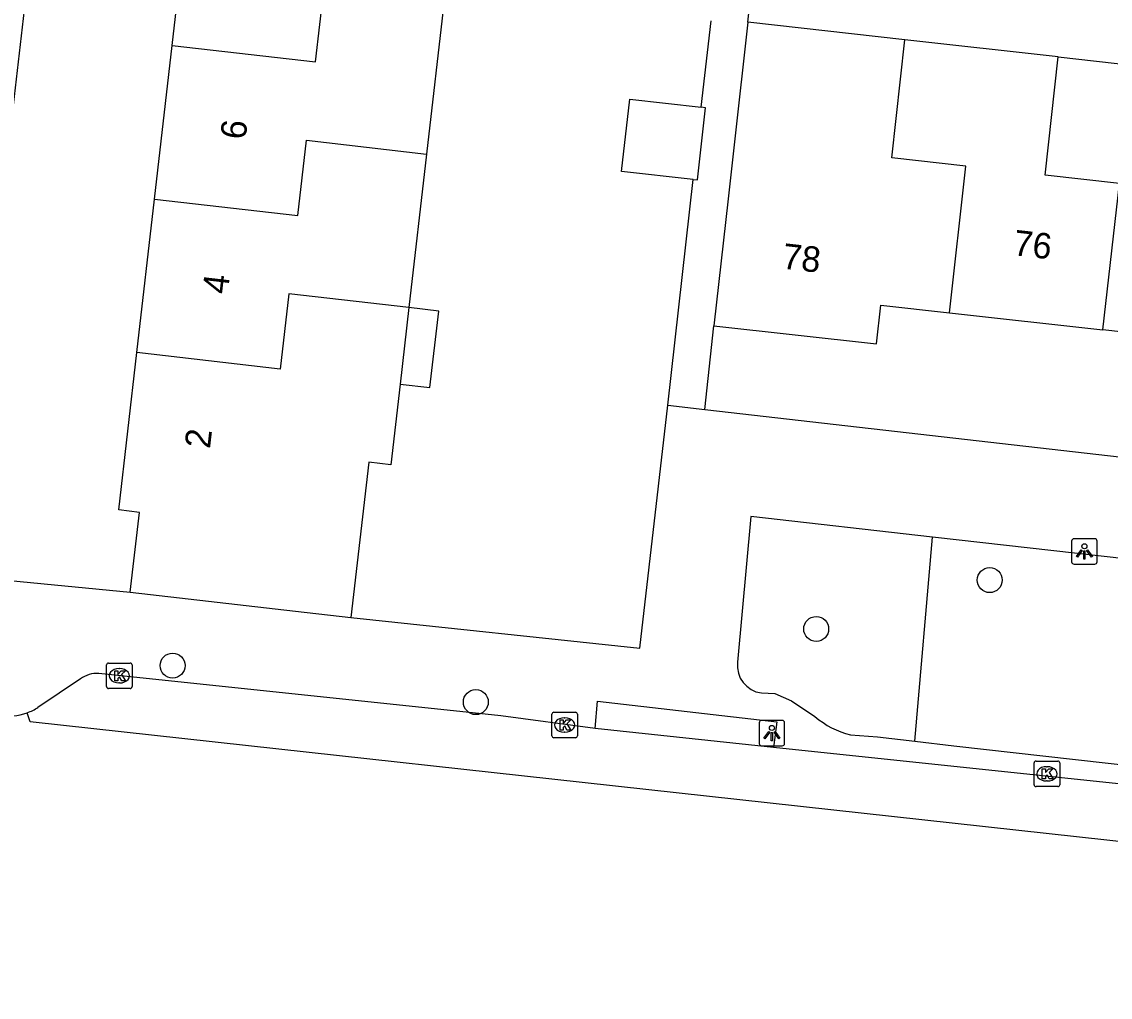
# Model space of a CAD drawing. Extents: x 162082 to 163393, y 388091 to 388632.
# Drawn here: x 162657.96 to 162700.61, y 388094.28 to 388132.52 of the extents above; entities that cross this region are included whole.
import ezdxf

# ---------------------------------------------------------------- set-up
doc = ezdxf.new("R2010")
doc.units = 0
for name, color, linetype in [('IMGEO_Boom', 7, 'Continuous'), ('IMGEO_Groenvoorziening', 7, 'Continuous'), ('IMGEO_Kolk', 7, 'Continuous'), ('IMGEO_Lichtpunt', 7, 'Continuous'), ('IMGEO_Pand', 7, 'Continuous'), ('IMGEO_Pand_nummerreeks', 7, 'Continuous'), ('IMGEO_Pand_overbouw', 7, 'Continuous'), ('IMGEO_Rijbaan_lokaal_gesloten', 7, 'Continuous'), ('IMGEO_Voetpad_open', 7, 'Continuous')]:
    doc.layers.add(name, color=color, linetype=linetype)

msp = doc.modelspace()

# ---------------------------------------------------------------- linework, layer by layer
at = {"layer": 'IMGEO_Boom'}
for centre in [(162695.889, 388110.633), (162689.089, 388108.721), (162663.87, 388107.283), (162675.753, 388105.851)]:
    msp.add_circle(centre, 0.489, dxfattribs=at)
at = {"layer": 'IMGEO_Groenvoorziening'}
msp.add_lwpolyline([(162692.953, 388104.317), (162693.647, 388112.321)], dxfattribs=at)
at = {"layer": 'IMGEO_Kolk'}
for p, q in [((162661.283, 388106.457), (162661.283, 388107.309)), ((162661.358, 388107.383), (162662.21, 388107.383)), ((162661.771, 388107.163), (162661.796, 388107.163)), ((162662.284, 388107.309), (162662.284, 388106.457)), ((162662.21, 388106.383), (162661.358, 388106.383)), ((162661.794, 388106.603), (162661.769, 388106.603)), ((162678.806, 388105.454), (162679.658, 388105.454)), ((162678.731, 388104.528), (162678.731, 388105.38)), ((162679.219, 388105.234), (162679.244, 388105.234)), ((162679.732, 388105.38), (162679.732, 388104.528)), ((162679.242, 388104.674), (162679.217, 388104.674)), ((162679.658, 388104.454), (162678.806, 388104.454)), ((162697.629, 388102.614), (162697.629, 388103.466)), ((162697.704, 388103.54), (162698.556, 388103.54)), ((162698.117, 388103.32), (162698.142, 388103.32)), ((162698.63, 388103.466), (162698.63, 388102.614)), ((162698.556, 388102.54), (162697.704, 388102.54)), ((162698.14, 388102.76), (162698.115, 388102.76))]:
    msp.add_line(p, q, dxfattribs=at)
for points in [[(162661.283, 388106.457), (162661.283, 388107.309)], [(162661.358, 388107.383), (162662.21, 388107.383)], [(162662.284, 388107.309), (162662.284, 388106.457)], [(162661.604, 388107.083), (162661.727, 388107.083), (162661.727, 388106.932), (162661.857, 388107.083), (162662.021, 388107.083), (162661.875, 388106.932), (162662.028, 388106.683), (162661.876, 388106.683), (162661.791, 388106.847), (162661.727, 388106.78), (162661.727, 388106.683), (162661.604, 388106.683), (162661.604, 388107.083)], [(162662.21, 388106.383), (162661.358, 388106.383)], [(162678.806, 388105.454), (162679.658, 388105.454)], [(162678.731, 388104.528), (162678.731, 388105.38)], [(162679.052, 388105.154), (162679.175, 388105.154), (162679.175, 388105.003), (162679.305, 388105.154), (162679.469, 388105.154), (162679.323, 388105.003), (162679.476, 388104.754), (162679.324, 388104.754), (162679.239, 388104.918), (162679.175, 388104.851), (162679.175, 388104.754), (162679.052, 388104.754), (162679.052, 388105.154)], [(162679.732, 388105.38), (162679.732, 388104.528)], [(162679.658, 388104.454), (162678.806, 388104.454)], [(162697.629, 388102.614), (162697.629, 388103.466)], [(162697.704, 388103.54), (162698.556, 388103.54)], [(162698.63, 388103.466), (162698.63, 388102.614)], [(162697.95, 388103.24), (162698.073, 388103.24), (162698.073, 388103.089), (162698.203, 388103.24), (162698.367, 388103.24), (162698.221, 388103.089), (162698.374, 388102.84), (162698.222, 388102.84), (162698.137, 388103.004), (162698.073, 388102.937), (162698.073, 388102.84), (162697.95, 388102.84), (162697.95, 388103.24)], [(162698.556, 388102.54), (162697.704, 388102.54)]]:
    msp.add_lwpolyline(points, dxfattribs=at)
for centre, start, end in [((162661.36, 388107.307), 91.552, 178.448), ((162661.36, 388107.307), 91.552, 178.448), ((162662.208, 388107.307), 1.552, 88.448), ((162662.208, 388107.307), 1.552, 88.448), ((162661.36, 388106.459), 181.552, 268.448), ((162661.36, 388106.459), 181.552, 268.448), ((162662.208, 388106.459), 271.552, 358.448), ((162662.208, 388106.459), 271.552, 358.448), ((162678.808, 388105.378), 91.552, 178.448), ((162678.808, 388105.378), 91.552, 178.448), ((162679.656, 388105.378), 1.552, 88.448), ((162679.656, 388105.378), 1.552, 88.448), ((162678.808, 388104.53), 181.552, 268.448), ((162678.808, 388104.53), 181.552, 268.448), ((162679.656, 388104.53), 271.552, 358.448), ((162679.656, 388104.53), 271.552, 358.448), ((162697.706, 388103.464), 91.552, 178.448), ((162697.706, 388103.464), 91.552, 178.448), ((162698.554, 388103.464), 1.552, 88.448), ((162698.554, 388103.464), 1.552, 88.448), ((162697.706, 388102.616), 181.552, 268.448), ((162697.706, 388102.616), 181.552, 268.448), ((162698.554, 388102.616), 271.552, 358.448), ((162698.554, 388102.616), 271.552, 358.448)]:
    msp.add_arc(centre, 0.0765, start, end, dxfattribs=at)
for centre, major_axis, ratio, start_param, end_param in [((162661.77, 388106.883), (-0.387, 0.002), 0.722429, 4.712389, 7.853982), ((162661.795, 388106.883), (-0.39, 0.002), 0.717154, 1.570796, 4.712389), ((162679.218, 388104.954), (-0.387, 0.002), 0.722429, 4.712389, 7.853982), ((162679.243, 388104.954), (-0.39, 0.002), 0.717154, 1.570796, 4.712389), ((162698.116, 388103.04), (-0.387, 0.002), 0.722429, 4.712389, 7.853982), ((162698.141, 388103.04), (-0.39, 0.002), 0.717154, 1.570796, 4.712389)]:
    msp.add_ellipse(centre, major_axis=major_axis, ratio=ratio, start_param=start_param, end_param=end_param, dxfattribs=at)
at = {"layer": 'IMGEO_Lichtpunt'}
for p, q in [((162699.099, 388112.161), (162699.099, 388111.354)), ((162699.099, 388112.161), (162699.099, 388111.354)), ((162700.001, 388112.256), (162699.193, 388112.256)), ((162700.001, 388112.256), (162699.193, 388112.256)), ((162700.095, 388111.354), (162700.095, 388112.161)), ((162700.095, 388111.354), (162700.095, 388112.161)), ((162699.193, 388111.26), (162700.001, 388111.26)), ((162699.193, 388111.26), (162700.001, 388111.26)), ((162686.855, 388105.039), (162686.855, 388104.232)), ((162686.855, 388105.039), (162686.855, 388104.232)), ((162687.757, 388105.134), (162686.949, 388105.134)), ((162687.757, 388105.134), (162686.949, 388105.134)), ((162687.851, 388104.232), (162687.851, 388105.039)), ((162687.851, 388104.232), (162687.851, 388105.039)), ((162686.949, 388104.138), (162687.757, 388104.138)), ((162686.949, 388104.138), (162687.757, 388104.138))]:
    msp.add_line(p, q, dxfattribs=at)
for points in [[(162699.473, 388111.825), (162699.512, 388111.797), (162699.324, 388111.535), (162699.286, 388111.562), (162699.473, 388111.825)], [(162699.575, 388111.777), (162699.622, 388111.777), (162699.622, 388111.455), (162699.575, 388111.455), (162699.575, 388111.777)], [(162699.685, 388111.797), (162699.723, 388111.824), (162699.91, 388111.562), (162699.871, 388111.534), (162699.685, 388111.797)], [(162687.229, 388104.703), (162687.268, 388104.675), (162687.08, 388104.413), (162687.042, 388104.44), (162687.229, 388104.703)], [(162687.331, 388104.655), (162687.378, 388104.655), (162687.378, 388104.333), (162687.331, 388104.333), (162687.331, 388104.655)], [(162687.441, 388104.675), (162687.479, 388104.702), (162687.666, 388104.44), (162687.627, 388104.412), (162687.441, 388104.675)]]:
    msp.add_lwpolyline(points, dxfattribs=at)
for centre in [(162699.598, 388111.959), (162687.354, 388104.837)]:
    msp.add_circle(centre, 0.0994, dxfattribs=at)
for centre, start, end in [((162699.193, 388112.161), 90, 180), ((162699.193, 388112.161), 90, 180), ((162700.001, 388112.161), 0, 90), ((162700.001, 388112.161), 0, 90), ((162699.193, 388111.354), 180, 270), ((162699.193, 388111.354), 180, 270), ((162700.001, 388111.354), 270, 0), ((162700.001, 388111.354), 270, 360), ((162686.949, 388105.039), 90, 180), ((162686.949, 388105.039), 90, 180), ((162687.757, 388105.039), 0, 90), ((162687.757, 388105.039), 0, 90), ((162686.949, 388104.232), 180, 270), ((162686.949, 388104.232), 180, 270), ((162687.757, 388104.232), 270, 0), ((162687.757, 388104.232), 270, 360)]:
    msp.add_arc(centre, 0.0946, start, end, dxfattribs=at)
at = {"layer": 'IMGEO_Pand'}
for points in [[(162663.853, 388131.589), (162664.545, 388137.607)], [(162663.853, 388131.589), (162669.472, 388130.944), (162669.81, 388133.889), (162674.513, 388133.345)], [(162674.513, 388133.345), (162673.821, 388127.33)], [(162686.416, 388132.5), (162685.892, 388127.817), (162685.641, 388125.574), (162685.085, 388120.605)], [(162692.567, 388131.812), (162686.416, 388132.5)], [(162663.161, 388125.571), (162663.853, 388131.589)], [(162694.308, 388121.112), (162694.953, 388126.856), (162692.052, 388127.181), (162692.567, 388131.812)], [(162698.577, 388131.139), (162692.567, 388131.812)], [(162700.324, 388120.439), (162700.969, 388126.183), (162698.058, 388126.508), (162698.577, 388131.139)], [(162698.577, 388131.139), (162704.584, 388130.467)], [(162684.27, 388126.338), (162681.465, 388126.651), (162681.782, 388129.481), (162684.587, 388129.167)], [(162684.27, 388126.338), (162684.437, 388126.319), (162684.753, 388129.148), (162684.587, 388129.167)], [(162663.161, 388125.571), (162668.78, 388124.925), (162669.119, 388127.874), (162673.821, 388127.33)], [(162673.821, 388127.33), (162673.129, 388121.316)], [(162662.469, 388119.553), (162663.161, 388125.571)], [(162673.129, 388121.316), (162668.427, 388121.86), (162668.088, 388118.908), (162662.469, 388119.553)], [(162673.129, 388121.316), (162672.784, 388118.318), (162672.421, 388115.157), (162671.557, 388115.256), (162670.857, 388109.168)], [(162685.085, 388120.605), (162691.446, 388119.894), (162691.616, 388121.413), (162694.308, 388121.112)], [(162694.308, 388121.112), (162700.324, 388120.439)], [(162706.341, 388119.765), (162700.324, 388120.439)], [(162662.214, 388110.161), (162662.574, 388113.29), (162661.759, 388113.384), (162662.469, 388119.553)], [(162662.214, 388110.161), (162668.681, 388109.418), (162670.857, 388109.168)]]:
    msp.add_lwpolyline(points, dxfattribs=at)
at = {"layer": 'IMGEO_Pand_overbouw'}
msp.add_lwpolyline([(162674.301, 388121.18), (162673.129, 388121.316), (162672.784, 388118.318), (162673.955, 388118.183)], close=True, dxfattribs=at)
at = {"layer": 'IMGEO_Rijbaan_lokaal_gesloten'}
msp.add_lwpolyline([(162891.178, 388094.283), (162862.144, 388094.92), (162728.664, 388097.932), (162718.662, 388098.447), (162658.296, 388105.083), (162658.176, 388105.434)], dxfattribs=at)
msp.add_arc((162657.462, 388107.376), 2.069, 259.0088, 290.176, dxfattribs=at)
at = {"layer": 'IMGEO_Voetpad_open'}
for points in [[(162661.941, 388166.636), (162655.964, 388114.983), (162655.74, 388113.043)], [(162686.416, 388132.5), (162687.422, 388141.491), (162750.73, 388134.453)], [(162684.587, 388129.167), (162684.969, 388132.561)], [(162683.276, 388117.486), (162684.27, 388126.338)], [(162684.724, 388117.321), (162685.085, 388120.605)], [(162670.857, 388109.168), (162682.179, 388107.971), (162683.276, 388117.486)], [(162683.276, 388117.486), (162684.724, 388117.321)], [(162684.724, 388117.321), (162748.067, 388110.086), (162748.395, 388113.098)], [(162693.647, 388112.321), (162686.525, 388113.123), (162686.009, 388107.417)], [(162740.958, 388106.991), (162693.647, 388112.321)], [(162657.492, 388110.617), (162662.214, 388110.161)], [(162660.263, 388106.758), (162658.597, 388105.646)], [(162680.434, 388104.818), (162676.729, 388105.31), (162660.98, 388106.977)], [(162680.434, 388104.818), (162680.522, 388105.889), (162687.541, 388105.077), (162687.414, 388104.072)], [(162686.943, 388106.209), (162687.467, 388106.192), (162688.127, 388105.907), (162689.042, 388105.286)], [(162687.414, 388104.072), (162680.434, 388104.818)], [(162690.43, 388104.563), (162691.487, 388104.484), (162692.953, 388104.317)], [(162692.953, 388104.317), (162694.484, 388104.143), (162717.155, 388101.594), (162724.293, 388101.205), (162738.752, 388100.665), (162740.923, 388100.643)], [(162744.969, 388099.668), (162734.332, 388099.937), (162723.767, 388100.411), (162721.042, 388100.533), (162687.414, 388104.072)]]:
    msp.add_lwpolyline(points, dxfattribs=at)
for centre, radius, start, end in [((162687.085, 388107.284), 1.084, 172.9434, 262.4775), ((162660.925, 388105.873), 1.106, 87.1704, 126.7991), ((162657.474, 388107.352), 2.043, 290.103, 303.3533), ((162691.273, 388107.875), 3.417, 229.2479, 255.7227)]:
    msp.add_arc(centre, radius, start, end, dxfattribs=at)

# ---------------------------------------------------------------- texts
at = {"layer": 'IMGEO_Pand_nummerreeks'}
for s, rotation, p in [('6', 83.4379, (162666.728, 388127.875)), ('76', 353.6149, (162696.784, 388123.372)), ('78', 353.6222, (162687.728, 388122.846)), ('4', 83.4379, (162666.031, 388121.819)), ('2', 83.4398, (162665.334, 388115.763))]:
    msp.add_text(s, height=1, rotation=rotation, dxfattribs=at).set_placement(p)

doc.saveas('drawing.dxf')
